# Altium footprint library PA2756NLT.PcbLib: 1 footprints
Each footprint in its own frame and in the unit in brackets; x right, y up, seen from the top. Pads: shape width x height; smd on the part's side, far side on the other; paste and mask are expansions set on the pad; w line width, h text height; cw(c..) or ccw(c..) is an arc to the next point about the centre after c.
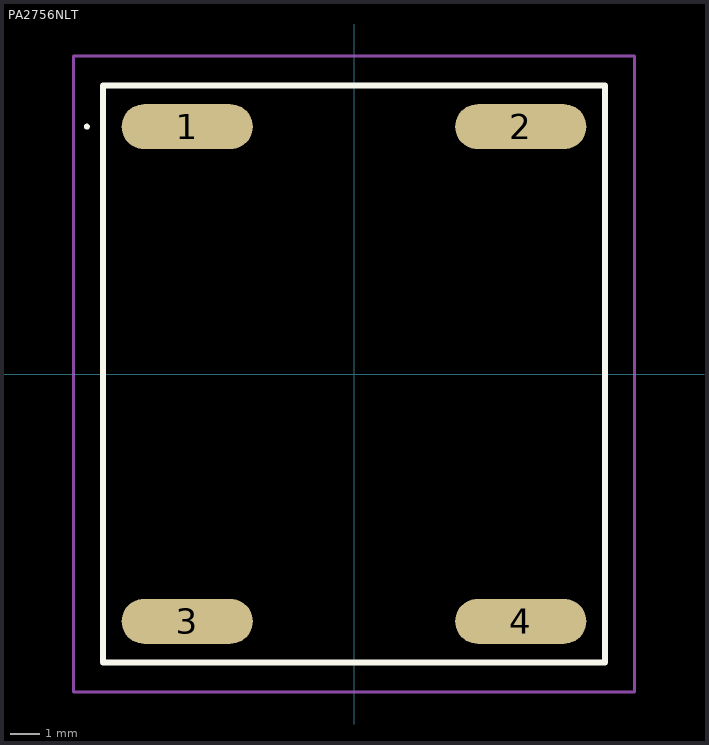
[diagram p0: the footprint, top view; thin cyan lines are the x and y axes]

## PA2756NLT [mm]
pads (4):
  oval 4.45x1.52 smd: 1(-5.65,8.38) 2(5.65,8.38) 3(-5.65,-8.38) 4(5.65,-8.38)
Top Overlay:
  lines w0.1: -9.1,8.38 cw(c-9.05,8.38) -9,8.38 ; -9.1,8.38 -9.1,8.38 ; -9.1,8.38 ccw(c-9.05,8.38) -9,8.38 ; -9,8.38 -9,8.38
  lines w0.2: -8.51,-9.78 8.51,-9.78 8.51,9.78 -8.51,9.78 -8.51,-9.78
Mechanical 15:
  lines w0.1: -8.51,-9.78 8.51,-9.78 8.51,9.78 -8.51,9.78 -8.51,-9.78
Mechanical 20:
  lines w0.1: -9.51,-10.78 9.51,-10.78 9.51,10.78 -9.51,10.78 -9.51,-10.78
